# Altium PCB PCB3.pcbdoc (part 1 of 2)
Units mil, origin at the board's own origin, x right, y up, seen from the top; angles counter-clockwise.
Board outline 2248.24 x 2229.86 mil, 2 copper layers (Top Layer, Bottom Layer); 104 components, 71 nets, 405 pads, 227 vias.
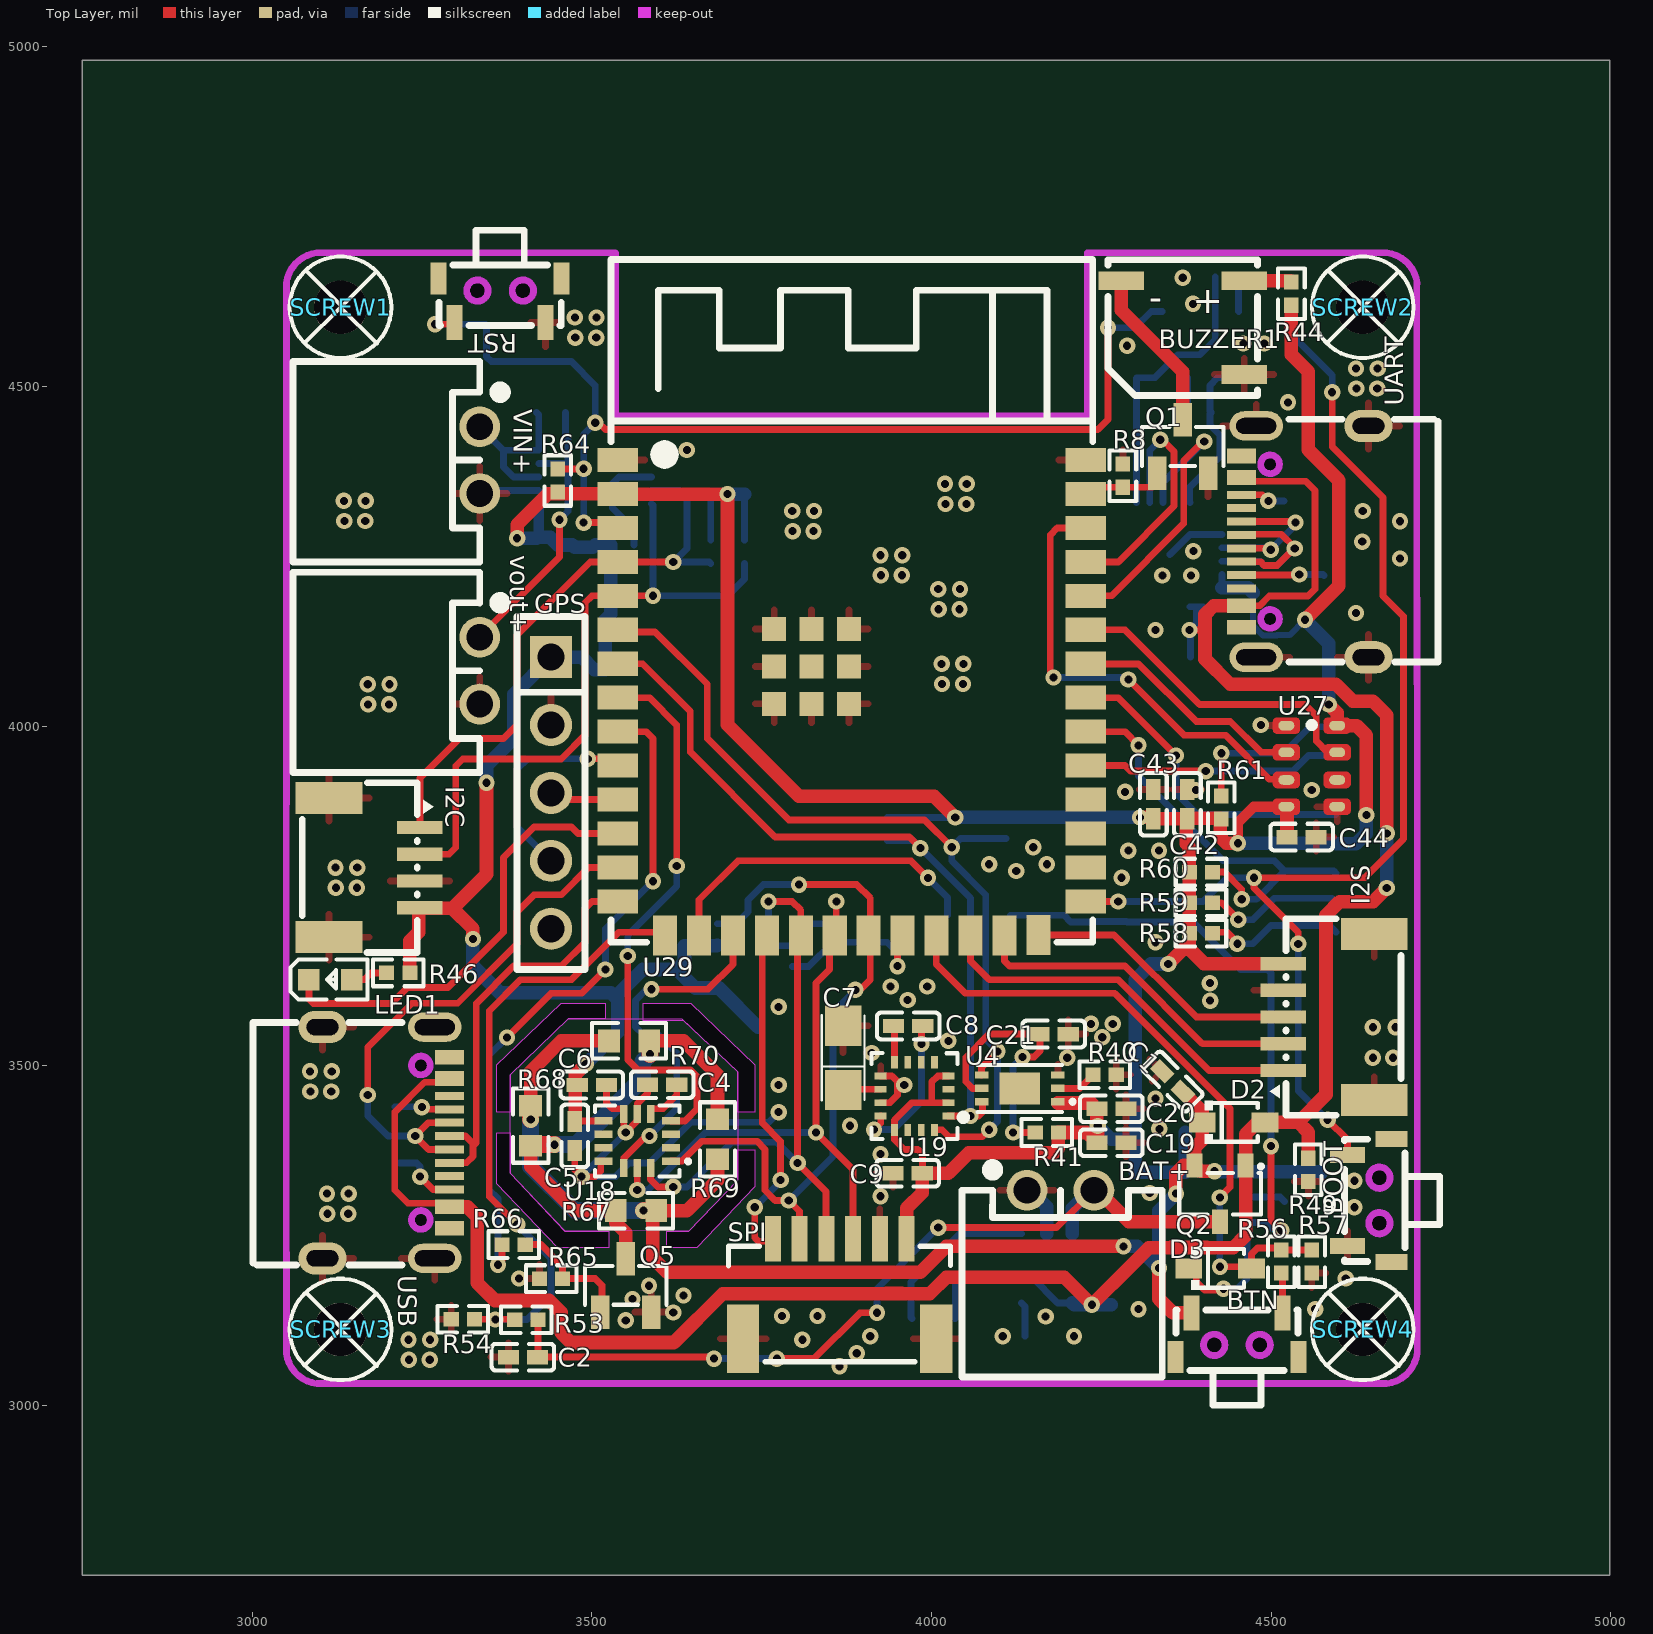
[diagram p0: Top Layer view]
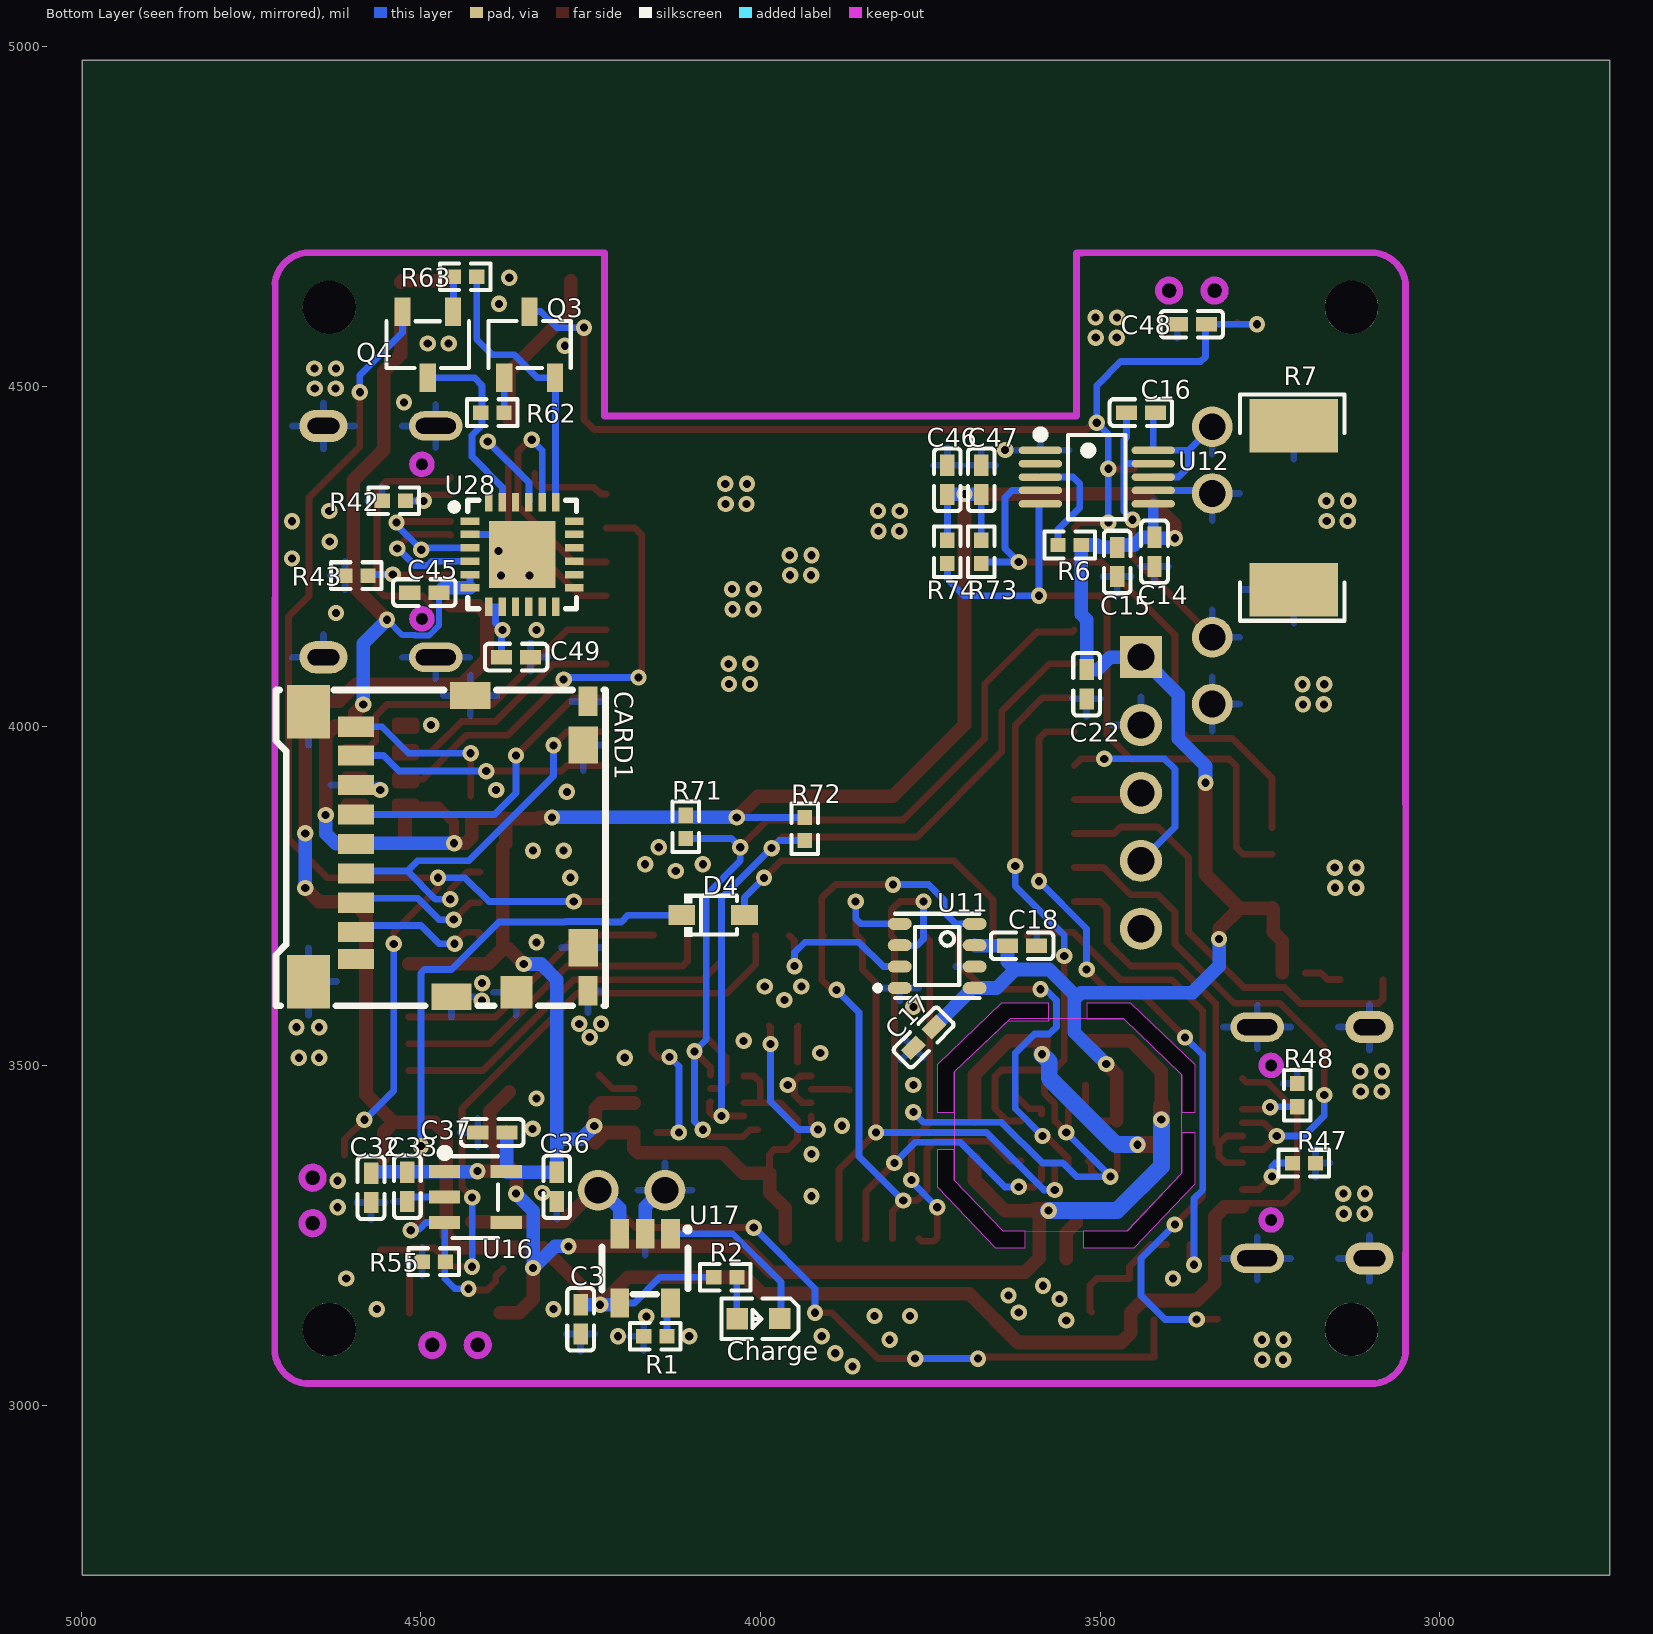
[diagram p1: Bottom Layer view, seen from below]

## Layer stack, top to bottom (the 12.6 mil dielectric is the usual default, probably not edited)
Top Layer: signal copper (thickness not stored)
Dielectric: dielectric 12.6, FR-4, Dk 4.8
Bottom Layer: signal copper (thickness not stored)

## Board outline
4998.24,2750 2750,2750 2750,4979.86 4998.24,4979.86
cut-out: 3519.88,3568.87 3464.93,3568.87 3379.88,3486.31 3379.88,3431.5 3359.99,3431.5 3359.99,3501.11 3455.02,3591.5 3519.88,3591.5
cut-out: 3379.8,3401.5 3379.8,3341.84 3460.07,3256.5 3524.88,3256.5 3524.88,3231.6 3450.03,3231.6 3359.88,3326.38 3359.88,3401.5
cut-out: 3715.09,3431.13 3715.09,3491.05 3635.26,3566.4 3575.33,3566.4 3575.33,3591.52 3645.34,3591.52 3739.88,3501.46 3739.88,3431.13
cut-out: 3609.99,3256.41 3642.26,3256.41 3714.88,3331.5 3714.88,3376.05 3740.01,3376.05 3740.01,3321.59 3654.37,3231.5 3609.99,3231.5

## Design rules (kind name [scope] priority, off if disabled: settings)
Clearance copperThickness1oz [All] p1: gap=7 ignorepadtopadclearanceinfootprint=FALSE except(4: Track-Track; 6: Track-SMDPad SMDPad-SMDPad Track-THPad SMDPad-THPad THPad-THPad Track-Via SMDPad-Via THPad-Via Via-Via SMDPad-Fill THPad-Fill Via-Fill Fill-Fill Track-Region SMDPad-Region THPad-Region Via-Region Region-Region Track-Poly SMDPad-Poly THPad-Poly Via-Poly Fill-Poly Region-Poly Poly-Poly Track-Text SMDPad-Text THPad-Text Via-Text Fill-Text Region-Text Poly-Text Text-Text; 6.9: Track-Hole SMDPad-Hole THPad-Hole Via-Hole Fill-Hole Region-Hole Poly-Hole Text-Hole Sheet-Hole; 11.8: Track-Fill Fill-Region Track-Sheet SMDPad-Sheet THPad-Sheet Via-Sheet Fill-Sheet Region-Sheet Poly-Sheet Text-Sheet)
Clearance copperThickness2oz [All] p1: gap=7 ignorepadtopadclearanceinfootprint=FALSE except(6: Track-SMDPad SMDPad-SMDPad Track-THPad SMDPad-THPad THPad-THPad Track-Via SMDPad-Via THPad-Via Via-Via SMDPad-Fill THPad-Fill Via-Fill Fill-Fill Track-Region SMDPad-Region THPad-Region Via-Region Region-Region Track-Poly SMDPad-Poly THPad-Poly Via-Poly Fill-Poly Region-Poly Poly-Poly Track-Text SMDPad-Text THPad-Text Via-Text Fill-Text Region-Text Poly-Text Text-Text; 6.9: Track-Hole SMDPad-Hole THPad-Hole Via-Hole Fill-Hole Region-Hole Poly-Hole Text-Hole Sheet-Hole; 8: Track-Track; 11.8: Track-Fill Fill-Region Track-Sheet SMDPad-Sheet THPad-Sheet Via-Sheet Fill-Sheet Region-Sheet Poly-Sheet Text-Sheet)
DiffPairsRouting differentialPair [All] p1: maxuncoupledlength=10 maxlimit=6 mostfreqgap=6 toplayer_minwidth=5 toplayer_prefwidth=10 toplayer_maxwidth=100 bottomlayer_minwidth=5 bottomlayer_prefwidth=10 bottomlayer_maxwidth=100
PasteMaskExpansion pasteMaskExpansion [All] p1:
PlaneConnect innerPlane [All] p1: planeconnectstyle=Relief reliefexpansion=20 reliefentries=4 reliefconductorwidth=10 reliefairgap=10
PolygonConnect copperRegion [All] p1: connectstyle=Relief reliefentries=4 reliefconductorwidth=10 polygonreliefangle="90 Angle" airgapwidth=10
RoutingVias viaSize [All] p1: viastyle="Through Hole" holewidth=12.0078 minholewidth=11.811 maxholewidth=248.0314 width=24.0158 minwidth=19.685 maxwidth=393.7008
SolderMaskExpansion solderMaskExpansion [All] p1: useseparateexpansions=TRUE expansion=2 expansionbottom=2
Width copperThickness1oz [All] p1: maxlimit=100 minlimit=5 preferedwidth=10
Width copperThickness2oz [All] p1: maxlimit=100 minlimit=8 preferedwidth=10

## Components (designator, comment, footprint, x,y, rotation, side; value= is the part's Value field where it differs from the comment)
BAT+ "XH2.54-2P_H弯针插座" CONN-TH_2P-P2.5_XH2.54-2P_H 4189.88,3316.5 r0 top
BOOT "1TS003B-1800-3500A-CT" SW-SMD_1TS003B-XXXX-3500A-CT#1 4644.88,3301.5 r270 top
BTN "1TS003B-1800-3500A-CT" SW-SMD_1TS003B-XXXX-3500A-CT#2 4449.81,3103.36 r180 top
BUZZER1 "MLT-5020" BUZ-SMD_L5.0-W5.5-P4.60 4369.88,4586.5 r180 top
C1 "CL05A106MQ5NUNC" C0402 4354.88,3476.5 r315 top
C2 "CL05A106MQ5NUNC" C0402 3398.5,3070.81 r180 top
C3 "CL05A106MQ5NUNC" C0402 4264.88,3126.5 r90 bottom
C4 "CC0402KRX7R7BB103" C0402 3603.5,3472.02 r180 top
C5 "CC0402KRX7R7BB104" C0402 3474.88,3396.5 r90 top
C6 "GRM155R61E225KE11D" C0402 3499.88,3471.5 r180 top
C7 "TAJA475K016RNJ" CASE-A_3216 3869.88,3511.5 r90 top
C8 "CL05B224KO5NNNC" C0402 3965.76,3558.36 r0 top
C9 "CC0402KRX7R7BB104" C0402 3964.88,3341.5 r0 top
C14 "CC0402KRX7R7BB104" C0402 3419.88,4256.5 r90 bottom
C15 "C1005X5R105KCTS" C0402 3474.88,4241.5 r90 bottom
C16 "CC0402KRX7R7BB104" C0402 3439.88,4461.5 r180 bottom
C17 "CC0402KRX7R7BB104" C0402 3759.88,3541.5 r135 bottom
C18 "C1005X5R105KCTS" C0402 3614.88,3676.5 r0 bottom
C19 "CC0402KRX7R7BB104" C0402 4264.88,3386.5 r180 top
C20 "C1005X5R105KCTS" C0402 4264.88,3436.5 r180 top
C21 "CC0402KRX7R7BB104" C0402 4179.88,3546.5 r180 top
C22 "CC0402KRX7R7BB104" C0402 3519.88,4061.5 r90 bottom
C32 "CL05A106MQ5NUNC" C0402 4573.42,3320.04 r90 bottom
C33 "CC0402KRX7R7BB104" C0402 4519.88,3321.5 r90 bottom
C36 "CL05A106MQ5NUNC" C0402 4299.88,3321.5 r90 bottom
C37 "CC0402KRX7R7BB104" C0402 4394.88,3401.5 r180 bottom
C42 "0603B104K500NT" C0402 4376.74,3884.9 r270 top
C43 "C1005X5R105KCTS" C0402 4326.74,3884.9 r270 top
C44 "CC0402KRX7R7BB104" C0402 4544.88,3836.5 r0 top
C45 "0603B104K500NT" C0402 4494.88,4196.5 r0 bottom
C46 "CC0402KRX7R7BB104" C0402 3724.88,4362.5 r90 bottom
C47 "C1005X5R105KCTS" C0402 3674.88,4362.5 r90 bottom
C48 "C1005X5R105KCTS" C0402 3364.88,4591.5 r0 bottom
C49 "CC0402KRX7R7BB104" C0402 4359.88,4101.5 r0 bottom
CARD1 "TF-110" TF-SMD_TF-110 4459.71,3823.2 r270 bottom
Charge "XL-1608SURC-06" LED0603-RD_RED 4002.88,3127.5 r0 bottom
D2 "1N5819WS_C191023" SOD-323_L1.8-W1.3-LS2.5-RD 4444.88,3416.5 r0 top
D3 "1N5819WS_C191023" SOD-323_L1.8-W1.3-LS2.5-RD 4424.88,3201.5 r0 top
D4 "1N5819WS_C191023" SOD-323_L1.8-W1.3-LS2.5-RD 4069.88,3721.5 r180 bottom
GPS "2.54-1*5P母" HDR-TH_5P-P2.54-V-F 3439.88,3901.5 r270 top
I2C "ZX-SH1.0-4PWT" CONN-SMD_4P-P1.00_MEGASTAR_ZX-SH1.0-4PWT 3179.88,3791.5 r270 top
I2S "ZX-SH1.0-5PWT" CONN-SMD_5P-P1.00_MEGASTAR_ZX-SH1.0-5PWT 4584.88,3571.5 r90 top
LED1 "XL-1608SURC-06" LED0603-RD_RED 3114.88,3626.5 r0 top
Q1 "SI2302-HXY" SOT-23-3_L2.9-W1.3-P1.90-LS2.4-BR 4369.88,4411.5 r270 top
Q2 "AO3401_C727156" SOT-23-3_L2.9-W1.4-P1.90-LS2.6-BR 4424.88,3311.5 r90 top
Q3 "S8050_C181158" SOT-23-3_L2.9-W1.6-P1.90-LS2.8-BR 4339.88,4561.5 r270 bottom
Q4 "S8050_C181158" SOT-23-3_L2.9-W1.6-P1.90-LS2.8-BR 4489.88,4561.5 r90 bottom
Q5 "AO3400A_C20917" SOT-23-3_L2.9-W1.3-P1.90-LS2.4-BR 3549.88,3176.5 r270 top
R1 "0402WGF2001TCE" R0402 4154.88,3101.5 r0 bottom
R2 "0402WGF3300TCE" R0402 4051.88,3188.5 r180 bottom
R6 "RTT02472JTH" R0402 3544.88,4266.5 r0 bottom
R7 "LRAN25EJER005" RES-SMD_L6.4-W3.2-R2512 3214.88,4321.5 r90 bottom
R8 "RC0402FR-0710KL" R0402 4281.88,4368.5 r270 top
R40 "RC0402FR-0710KL" R0402 4254.88,3486.5 r180 top
R41 "0402WGF1001TCE" R0402 4169.88,3401.5 r0 top
R42 "0402WGF5101TCE" R0402 4539.88,4331.5 r0 bottom
R43 "0402WGF5101TCE" R0402 4594.88,4221.5 r0 bottom
R44 "0402WGF220KTCE" R0402 4529.88,4636.5 r270 top
R46 "0402WGF1001TCE" R0402 3214.88,3636.5 r0 top
R47 "0402WGF5101TCE" R0402 3199.88,3356.5 r180 bottom
R48 "0402WGF5101TCE" R0402 3209.88,3456.5 r90 bottom
R49 "0402WGF2003TCE" R0402 4554.88,3346.5 r90 top
R53 "0402WGF5103TCE" R0402 3403.5,3125.81 r0 top
R54 "0402WGF5103TCE" R0402 3309.88,3126.5 r0 top
R55 "RC0402FR-0710KL" R0402 4480.88,3211.5 r180 bottom
R56 "0402WGF2001TCE" R0402 4514.88,3211.5 r90 top
R57 "0402WGF5101TCE" R0402 4559.88,3211.5 r270 top
R58 "RC0402FR-0710KL" R0402 4396.74,3694.9 r0 top
R59 "RC0402FR-0710KL" R0402 4396.74,3739.9 r0 top
R60 "RC0402FR-0710KL" R0402 4396.74,3784.9 r0 top
R61 "RC0402FR-0710KL" R0402 4426.74,3879.9 r90 top
R62 "RC0402FR-0710KL" R0402 4394.88,4461.5 r180 bottom
R63 "RC0402FR-0710KL" R0402 4434.88,4661.5 r0 bottom
R64 "RC0402FR-0710KL" R0402 3449.88,4361.5 r90 top
R65 "RC0402FR-0710KL" R0402 3439.88,3186.5 r180 top
R66 "0402WGJ0101TCE" R0402 3384.88,3236.5 r0 top
R67 "0603WAF510JT5E" R0603 3564.88,3286.5 r0 top
R68 "0603WAF510JT5E" R0603 3409.88,3411.5 r90 top
R69 "0603WAF510JT5E" R0603 3684.88,3391.5 r270 top
R70 "0603WAF510JT5E" R0603 3554.88,3536.5 r180 top
R71 "0402WGJ0472TCE" R0402 4109.88,3851.5 r90 bottom
R72 "0402WGJ0472TCE" R0402 3934.88,3848.5 r90 bottom
R73 "0402WGJ0472TCE" R0402 3674.88,4256.5 r270 bottom
R74 "0402WGJ0472TCE" R0402 3724.88,4256.5 r270 bottom
RST "1TS003B-1800-3500A-CT" SW-SMD_1TS003B-XXXX-3500A-CT#2 3364.88,4626.5 r0 top
SCREW1 "M2螺丝" M2螺丝 3129.88,4616.5 r0 top
SCREW2 "M2螺丝" M2螺丝 4634.88,4616.5 r0 top
SCREW3 "M2螺丝" M2螺丝 3129.88,3111.5 r0 top
SCREW4 "M2螺丝" M2螺丝 4634.88,3111.5 r0 top
SPI "AFC10-S06QCA-00" CONN-SMD_AFC10-S06QCA-00 3864.88,3171.5 r0 top
U4 "BH1750FVI-TR" WSOF-6_L2.6-W1.6-P0.50-TL-EP 4129.88,3466.5 r180 top
U11 "BME680" LGA-8_L3.0-W3.0-P0.80-TR 3739.88,3661.5 r0 bottom
U12 "INA226AIDGSR" MSOP-10_L3.0-W3.0-P0.50-LS5.0-BL 3504.88,4366.5 r270 bottom
U16 "RT9013-33GB" SOT-23-5_L3.0-W1.7-P0.95-LS2.8-BL 4419.88,3306.5 r270 bottom
U17 "TP4054_C668215" TSOT-23-5_L2.9-W1.6-P0.95-LS2.8-BR 4169.88,3201.5 r90 bottom
U18 "ICM-42688-P" LGA-14_L3.0-W2.5-P0.50-TL 3566.68,3389.08 r180 top
U19 "QMC5883L" LGA-16_L3.0-W3.0-P0.50-BL_SQ 3974.98,3455.25 r90 top
U27 "MSM261S4030H0" MSM-MIC 4559.88,3941.5 r180 top
U28 "CH9102F" QFN-24_L4.0-W4.0-P0.50-BL-EP2.5 4350.88,4252.5 r270 bottom
U29 "ESP32-S3-WROOM-1-N16R8" WIRELM-SMD_ESP32-S3-WROOM-1 3882.56,4041.5 r0 top
UART "TYPE-C 16PIN 2MD(073)" USB-C-SMD_TYPE-C-6PIN-2MD-073 4549.88,4271.5 r90 top
USB "TYPE-C 16PIN 2MD(073)" USB-C-SMD_TYPE-C-6PIN-2MD-073 3196.88,3386.5 r270 top
VIN+ "XH2.54-2P_H弯针插座" CONN-TH_2P-P2.5_XH2.54-2P_H 3334.88,4391.5 r270 top
vout+ "XH2.54-2P_H弯针插座" CONN-TH_2P-P2.5_XH2.54-2P_H 3334.88,4081.5 r270 top

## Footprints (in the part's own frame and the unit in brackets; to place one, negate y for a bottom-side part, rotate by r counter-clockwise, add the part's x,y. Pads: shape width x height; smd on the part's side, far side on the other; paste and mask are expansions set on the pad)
BUZ-SMD_L5.0-W5.5-P4.60 [mm]
  rect 1.7x0.7 smd: 1(-2.3,-1.75) 2(2.3,-1.75) 3(-2.3,1.75)
  silkscreen extent -2.79,-2.54 2.79,2.54
C0402 [mm]
  rect 0.79x0.54 smd: 1(-0.545,0) 2(0.545,0)
  silkscreen extent -1.17,-0.5 1.17,0.5
CASE-A_3216 [mil]
  rect 59.05x53.5 smd: 1(-47.24,0) 2(47.24,0)
  silkscreen extent -63,-32 63,32
CONN-SMD_4P-P1.00_MEGASTAR_ZX-SH1.0-4PWT [mm]
  rect 0.5x1.7 smd: 1(-1.5,1.7) 2(-0.5,1.7) 3(0.5,1.7) 4(1.5,1.7)
  rect 1.2x2.5 smd: 5(2.6,-1.7) 6(-2.6,-1.7)
  silkscreen extent -3.18,-2.7 3.18,2.21
CONN-SMD_5P-P1.00_MEGASTAR_ZX-SH1.0-5PWT [mm]
  rect 0.5x1.7 smd: 1(-2,1.7) 2(-1,1.7) 3(0,1.7) 4(1,1.7) 5(2,1.7)
  rect 1.2x2.5 smd: 6(3.1,-1.7) 7(-3.1,-1.7)
  silkscreen extent -3.67,-2.7 3.68,2.21
CONN-SMD_AFC10-S06QCA-00 [mm]
  rect 0.6x1.71 smd: 1(-2.5,1.87) 2(-1.5,1.87) 3(-0.5,1.87) 4(0.5,1.87) 5(1.5,1.87) 6(2.5,1.87)
  rect 1.2x2.55 smd: 7(3.61,-1.87) 8(-3.61,-1.87)
  silkscreen extent -4.16,-2.73 4.14,1.59
CONN-TH_2P-P2.5_XH2.54-2P_H [mil]
  round 60 hole 39.4: 1(-49.2,0) 2(49.2,0)
  silkscreen extent -145,-275 150,38
HDR-TH_5P-P2.54-V-F [mil]
  rect 62x62 hole 40.16: 1(-200,0)
  round 62 hole 40.16: 2(-100,0) 3(0,0) 4(100,0) 5(200,0)
  silkscreen extent -260,-50 260,50
LED0603-RD_RED [mm]
  rect 0.8x0.8 smd: 1(-0.8,-0.003) 2(0.8,0.003)
  silkscreen extent -1.49,-0.75 1.39,0.76
LGA-8_L3.0-W3.0-P0.80-TR [mm]
  oval 0.9x0.448 smd: 1(1.4,1.2) 2(1.4,0.4) 3(1.4,-0.4) 4(1.4,-1.2) 5(-1.4,-1.2) 6(-1.4,-0.4) 7(-1.4,0.4) 8(-1.4,1.2)
  silkscreen extent -1.58,-1.58 2.33,1.58
LGA-14_L3.0-W2.5-P0.50-TL [mm]
  rect 0.675x0.28 smd: 1(-1.262,0.75) 2(-1.262,0.25) 3(-1.262,-0.25) 4(-1.262,-0.75) 8(1.262,-0.75) 9(1.262,-0.25) 10(1.262,0.25) 11(1.262,0.75)
  rect 0.28x0.675 smd: 5(-0.5,-1.012) 6(0,-1.012) 7(0.5,-1.012) 12(0.5,1.012) 13(0,1.012) 14(-0.5,1.012)
  silkscreen extent -1.98,-1.33 1.58,1.33
LGA-16_L3.0-W3.0-P0.50-BL_SQ [mm]
  rect 0.25x0.45 smd: 1(-0.75,-1.263) 2(-0.25,-1.263) 3(0.25,-1.263) 4(0.75,-1.263) 9(0.75,1.263) 10(0.25,1.263) 11(-0.25,1.263) 12(-0.75,1.263)
  rect 0.45x0.25 smd: 5(1.263,-0.75) 6(1.263,-0.25) 7(1.263,0.25) 8(1.263,0.75) 13(-1.263,0.75) 14(-1.263,0.25) 15(-1.263,-0.25) 16(-1.263,-0.75)
  silkscreen extent -1.61,-1.95 1.61,1.6
M2螺丝 [mm]
  round 2 hole 2: 1(0,0)
  silkscreen extent -1.9,-1.9 1.9,1.9
MSM-MIC [mil]
  oval 23.64x14.16 smd: 1(-37.4,60.3) 3(-37.4,-19.7) 6(37.4,-19.7) 8(37.4,60.3)
  oval 23.64x14.22 smd: 2(-37.4,20.9) 4(-37.4,-59.1) 5(37.4,-59.1) 7(37.4,20.9)
  Top Layer region: -17.7,-13.8 -17.7,-25.6 -17.7,-25.6 -18.15,-27.86 -19.43,-29.77 -21.34,-31.05 -23.6,-31.5 -23.6,-31.5 -23.6,-31.5 -51.2,-31.5 -51.2,-31.5 -53.46,-31.05 -55.37,-29.77 -56.65,-27.86 -57.1,-25.6 -57.1,-25.6 -57.1,-25.6 -57.1,-13.8 -57.1,-13.8 -56.65,-11.54 -55.37,-9.63 -53.46,-8.35 -51.2,-7.9 -51.2,-7.9 -51.2,-7.9 -23.6,-7.9 -23.6,-7.9 -21.34,-8.35 -19.43,-9.63 -18.15,-11.54 -17.7,-13.8
  Top Layer region: -17.7,-53.1 -17.7,-65 -17.7,-65 -18.15,-67.26 -19.43,-69.17 -21.34,-70.45 -23.6,-70.9 -23.6,-70.9 -23.6,-70.9 -51.2,-70.9 -51.2,-70.9 -53.46,-70.45 -55.37,-69.17 -56.65,-67.26 -57.1,-65 -57.1,-65 -57.1,-65 -57.1,-53.1 -57.1,-53.1 -56.65,-50.84 -55.37,-48.93 -53.46,-47.65 -51.2,-47.2 -51.2,-47.2 -51.2,-47.2 -23.6,-47.2 -23.6,-47.2 -21.34,-47.65 -19.43,-48.93 -18.15,-50.84 -17.7,-53.1
  Top Layer region: -17.7,26.9 -17.7,15 -17.7,15 -18.15,12.74 -19.43,10.83 -21.34,9.55 -23.6,9.1 -23.6,9.1 -23.6,9.1 -51.2,9.1 -51.2,9.1 -53.46,9.55 -55.37,10.83 -56.65,12.74 -57.1,15 -57.1,15 -57.1,15 -57.1,26.9 -57.1,26.9 -56.65,29.16 -55.37,31.07 -53.46,32.35 -51.2,32.8 -51.2,32.8 -51.2,32.8 -23.6,32.8 -23.6,32.8 -21.34,32.35 -19.43,31.07 -18.15,29.16 -17.7,26.9
  Top Layer region: -17.7,66.2 -17.7,54.4 -17.7,54.4 -18.15,52.14 -19.43,50.23 -21.34,48.95 -23.6,48.5 -23.6,48.5 -23.6,48.5 -51.2,48.5 -51.2,48.5 -53.46,48.95 -55.37,50.23 -56.65,52.14 -57.1,54.4 -57.1,54.4 -57.1,54.4 -57.1,66.2 -57.1,66.2 -56.65,68.46 -55.37,70.37 -53.46,71.65 -51.2,72.1 -51.2,72.1 -51.2,72.1 -23.6,72.1 -23.6,72.1 -21.34,71.65 -19.43,70.37 -18.15,68.46 -17.7,66.2
  Top Layer region: 57.1,66.2 57.1,54.4 57.1,54.4 56.65,52.14 55.37,50.23 53.46,48.95 51.2,48.5 51.2,48.5 51.2,48.5 23.6,48.5 23.6,48.5 21.34,48.95 19.43,50.23 18.15,52.14 17.7,54.4 17.7,54.4 17.7,54.4 17.7,54.4 17.7,66.2 17.7,66.2 18.15,68.46 19.43,70.37 21.34,71.65 23.6,72.1 23.6,72.1 23.6,72.1 51.2,72.1 51.2,72.1 53.46,71.65 55.37,70.37 56.65,68.46 57.1,66.2
  Top Layer region: 57.1,26.9 57.1,15 57.1,15 56.65,12.74 55.37,10.83 53.46,9.55 51.2,9.1 51.2,9.1 51.2,9.1 23.6,9.1 23.6,9.1 21.34,9.55 19.43,10.83 18.15,12.74 17.7,15 17.7,15 17.7,15 17.7,15 17.7,26.9 17.7,26.9 18.15,29.16 19.43,31.07 21.34,32.35 23.6,32.8 23.6,32.8 23.6,32.8 51.2,32.8 51.2,32.8 53.46,32.35 55.37,31.07 56.65,29.16 57.1,26.9
  Top Layer region: 57.1,-53.1 57.1,-65 57.1,-65 56.65,-67.26 55.37,-69.17 53.46,-70.45 51.2,-70.9 51.2,-70.9 51.2,-70.9 23.6,-70.9 23.6,-70.9 21.34,-70.45 19.43,-69.17 18.15,-67.26 17.7,-65 17.7,-65 17.7,-65 17.7,-65 17.7,-53.1 17.7,-53.1 18.15,-50.84 19.43,-48.93 21.34,-47.65 23.6,-47.2 23.6,-47.2 23.6,-47.2 51.2,-47.2 51.2,-47.2 53.46,-47.65 55.37,-48.93 56.65,-50.84 57.1,-53.1
  Top Layer region: 57.1,-13.8 57.1,-25.6 57.1,-25.6 56.65,-27.86 55.37,-29.77 53.46,-31.05 51.2,-31.5 51.2,-31.5 51.2,-31.5 23.6,-31.5 23.6,-31.5 21.34,-31.05 19.43,-29.77 18.15,-27.86 17.7,-25.6 17.7,-25.6 17.7,-25.6 17.7,-25.6 17.7,-13.8 17.7,-13.8 18.15,-11.54 19.43,-9.63 21.34,-8.35 23.6,-7.9 23.6,-7.9 23.6,-7.9 51.2,-7.9 51.2,-7.9 53.46,-8.35 55.37,-9.63 56.65,-11.54 57.1,-13.8
  silkscreen extent -4,-64 4,-56
MSOP-10_L3.0-W3.0-P0.50-LS5.0-BL [mm]
  oval 0.28x1.62 smd: 1(-1,-2.11) 2(-0.5,-2.11) 3(0,-2.11) 4(0.5,-2.11) 5(1,-2.11) 6(1,2.11) 7(0.5,2.11) 8(0,2.11) 9(-0.5,2.11) 10(-1,2.11)
  silkscreen extent -1.74,-2.26 1.58,1.07
QFN-24_L4.0-W4.0-P0.50-BL-EP2.5 [mm]
  rect 0.28x0.7 smd: 1(-1.25,-1.95) 2(-0.75,-1.95) 3(-0.25,-1.95) 4(0.25,-1.95) 5(0.75,-1.95) 6(1.25,-1.95) 13(1.25,1.95) 14(0.75,1.95) 15(0.25,1.95) 16(-0.25,1.95) 17(-0.75,1.95) 18(-1.25,1.95)
  rect 0.7x0.28 smd: 7(1.95,-1.25) 8(1.95,-0.75) 9(1.95,-0.25) 10(1.95,0.25) 11(1.95,0.75) 12(1.95,1.25) 19(-1.95,1.25) 20(-1.95,0.75) 21(-1.95,0.25) 22(-1.95,-0.25) 23(-1.95,-0.75) 24(-1.95,-1.25)
  rect 2.5x2.5 smd: 25(0,0)
  silkscreen extent -2.03,-2.67 2.03,2.03
R0402 [mm]
  rect 0.566x0.54 smd: 1(-0.433,0) 2(0.433,0)
  silkscreen extent -0.94,-0.5 0.94,0.5
R0603 [mil]
  rect 31.75x34.02 smd: 1(-29.66,0) 2(29.66,0)
  silkscreen extent -55,-26 55,26
RES-SMD_L6.4-W3.2-R2512 [mm]
  rect 2x3.3 smd: 1(-3.066,0) 2(3.066,0)
  silkscreen extent -4.23,-1.91 4.23,2.01
SOD-323_L1.8-W1.3-LS2.5-RD [mm]
  rect 1x0.75 smd: 1(-1.173,0) 2(1.173,0)
  silkscreen extent -1.08,-0.8 0.9,0.8
SOT-23-3_L2.9-W1.3-P1.90-LS2.4-BR [mm]
  rect 1.25x0.7 smd: 1(1,-0.95) 2(1,0.95) 3(-1,0)
  silkscreen extent -0.73,-1.53 0.73,1.53
SOT-23-3_L2.9-W1.4-P1.90-LS2.6-BR [mm]
  rect 0.91x0.6 smd: 1(1.055,-0.955) 2(1.055,0.955) 3(-1.055,0)
  silkscreen extent -0.78,-1.6 1.09,1.53
SOT-23-3_L2.9-W1.6-P1.90-LS2.8-BR [mm]
  rect 1.07x0.6 smd: 1(1.235,-0.95) 2(1.235,0.95) 3(-1.235,0)
  silkscreen extent -0.88,-1.54 0.88,1.54
SOT-23-5_L3.0-W1.7-P0.95-LS2.8-BL [mm]
  rect 0.49x1.157 smd: 1(-0.95,-1.154) 2(0,-1.154) 3(0.95,-1.154)
  rect 0.49x1.175 smd: 4(0.95,1.154) 5(-0.95,1.154)
  silkscreen extent -1.8,-1.29 1.53,0.85
SW-SMD_1TS003B-XXXX-3500A-CT#1 [mm]
  rect 0.6x1.3 smd: 1(-1.7,-0.825) 2(1.7,-0.825)
  rect 0.6x1.2 smd: 3(2.3,0.825) 4(-2.3,0.825)
  Multi-Layer board cut-out: -0.85,0.77 -1.05,0.716 -1.196,0.57 -1.25,0.37 -1.196,0.17 -1.05,0.024 -0.85,-0.03 -0.85,-0.03 -0.676,0.01 -0.537,0.121 -0.46,0.281 -0.46,0.459 -0.537,0.619 -0.676,0.73 -0.85,0.77
  Multi-Layer board cut-out: 0.85,0.77 0.65,0.716 0.504,0.57 0.45,0.37 0.504,0.17 0.65,0.024 0.85,-0.03 0.85,-0.03 1.024,0.01 1.163,0.121 1.24,0.281 1.24,0.459 1.163,0.619 1.024,0.73 0.85,0.77
  Multi-Layer keep-out circle w0.254: c-0.85,0.37 r0.4
  Multi-Layer keep-out circle w0.254: c0.85,0.37 r0.4
  silkscreen extent -2.29,-0.94 2.29,2.63
SW-SMD_1TS003B-XXXX-3500A-CT#2 [mm]
  rect 0.6x1.3 smd: 1(-1.7,-0.825) 2(1.7,-0.825)
  rect 0.6x1.2 smd: 3(2.3,0.825) 4(-2.3,0.825)
  Multi-Layer board cut-out: -1.25,0.37 -1.195,0.171 -1.049,0.026 -0.85,-0.027 -0.651,0.026 -0.505,0.171 -0.45,0.37 -0.45,0.37 -0.505,0.569 -0.651,0.714 -0.85,0.767 -1.049,0.714 -1.195,0.569 -1.25,0.37
  Multi-Layer board cut-out: 0.45,0.37 0.505,0.171 0.651,0.026 0.85,-0.027 1.049,0.026 1.195,0.171 1.25,0.37 1.25,0.37 1.195,0.569 1.049,0.714 0.85,0.767 0.651,0.714 0.505,0.569 0.45,0.37
  Multi-Layer keep-out circle w0.254: c-0.85,0.37 r0.4
  Multi-Layer keep-out circle w0.254: c0.85,0.37 r0.4
  silkscreen extent -2.29,-0.94 2.29,2.63
TF-SMD_TF-110 [mil]
  rect 29.5x53.2 smd: 1(126.7,-136) 2(83.4,-136) 3(40.1,-136) 4(-3.2,-136) 5(-46.6,-136) 6(-89.9,-136) 7(-133.2,-136) 8(-175.7,-136) 9(166,-136)
  rect 47.2x47.2 smd: 10(215.2,100.2)
  rect 43.3x27.6 smd: 11(213.2,205.9) 14(-213.1,205.9)
  rect 55.1x43.3 smd: 12(149.4,198.6) 13(-148.9,198.6)
  rect 39.4x59.1 smd: 15(-221.7,32.3) 18(221.7,4.7)
  rect 78.7x63 smd: 16(-198.1,-205.9) 17(199.5,-205.9)
  silkscreen extent -230,-254 235,231
TSOT-23-5_L2.9-W1.6-P0.95-LS2.8-BR [mm]
  rect 1.1x0.7 smd: 1(1.294,-0.951) 2(1.294,-0.001) 3(1.294,0.951) 4(-1.294,0.951) 5(-1.294,-0.949)
  silkscreen extent -0.97,-1.65 1.52,1.61
USB-C-SMD_TYPE-C-6PIN-2MD-073 [mm]
  rect 0.55x1.1 smd: 1(-3.2,2.375) 2(-2.4,2.375) 11(2.4,2.375) 12(3.2,2.375)
  rect 0.3x1.1 smd: 3(-1.75,2.375) 4(-1.25,2.375) 5(-0.75,2.375) 6(-0.25,2.375) 7(0.25,2.375) 8(0.75,2.375) 9(1.25,2.375) 10(1.75,2.375)
  oval 1.2x1.8 hole 0.6 slot 1.2 at 90 deg: 13(-4.325,-2.375) 14(4.325,-2.375)
  oval 1.1x2 hole 0.6 slot 1.5 at 90 deg: 13(-4.325,1.825) 14(4.325,1.825)
  Multi-Layer board cut-out: -2.89,0.955 -2.716,1.003 -2.589,1.131 -2.543,1.305 -2.589,1.479 -2.716,1.607 -2.89,1.655 -2.89,1.655 -3.064,1.607 -3.191,1.479 -3.237,1.305 -3.191,1.131 -3.064,1.003 -2.89,0.955
  Multi-Layer board cut-out: 2.89,0.955 3.064,1.003 3.191,1.131 3.237,1.305 3.191,1.479 3.064,1.607 2.89,1.655 2.89,1.655 2.716,1.607 2.589,1.479 2.543,1.305 2.589,1.131 2.716,1.003 2.89,0.955
  Multi-Layer keep-out circle w0.254: c-2.89,1.305 r0.35
  Multi-Layer keep-out circle w0.254: c2.89,1.305 r0.35
  silkscreen extent -4.5,-4.97 4.57,0.6
WIRELM-SMD_ESP32-S3-WROOM-1 [mm]
  rect 1.5x0.9 smd: 1(-8.75,8.895) 2(-8.75,7.625) 3(-8.75,6.355) 4(-8.75,5.085) 5(-8.75,3.815) 6(-8.75,2.545) 7(-8.75,1.275) 8(-8.75,0.005) 9(-8.75,-1.265) 10(-8.75,-2.535) 11(-8.75,-3.805) 12(-8.75,-5.075) 13(-8.75,-6.345) 14(-8.75,-7.615) 27(8.75,-7.615) 28(8.75,-6.345) 29(8.75,-5.075) 30(8.75,-3.805) 31(8.75,-2.535) 32(8.75,-1.265) 33(8.75,0.005) 34(8.75,1.275) 35(8.75,2.545) 36(8.75,3.815) 37(8.75,5.085) 38(8.75,6.355) 39(8.75,7.625) 40(8.75,8.895)
  rect 0.9x1.5 smd: 15(-6.985,-8.895) 16(-5.715,-8.895) 17(-4.445,-8.895) 18(-3.175,-8.895) 19(-1.905,-8.895) 20(-0.635,-8.895) 21(0.635,-8.895) 22(1.905,-8.895) 23(3.175,-8.895) 24(4.445,-8.895) 25(5.715,-8.895) 26(6.985,-8.865)
  rect 0.9x0.9 smd: 41(-2.9,-0.225) 41(-2.9,1.175) 41(-2.9,2.575) 41(-1.5,-0.225) 41(-1.5,1.175) 41(-1.5,2.575) 41(-0.1,-0.225) 41(-0.1,1.175) 41(-0.1,2.575)
  silkscreen extent -9,-9.14 9.02,16.39
WSOF-6_L2.6-W1.6-P0.50-TL-EP [mm]
  rect 0.505x0.28 smd: 1(-1.427,0.5) 2(-1.427,0) 3(-1.427,-0.5) 4(1.427,-0.5) 5(1.427,0) 6(1.427,0.5)
  rect 1.5x1.2 smd: 7(0,0)
  silkscreen extent -2.05,-0.88 1.58,0.88

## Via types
v1: diameter 24.02, hole 12.01, Top Layer to Bottom Layer, 222 vias
v2: diameter 24, hole 12, Top Layer to Bottom Layer, 5 vias

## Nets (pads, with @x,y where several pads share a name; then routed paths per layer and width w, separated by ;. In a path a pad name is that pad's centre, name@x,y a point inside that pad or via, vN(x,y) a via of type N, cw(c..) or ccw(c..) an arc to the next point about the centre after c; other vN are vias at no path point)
3.3V: C5.2 C6.2 C9.2 C14.2 C15.2 C17.2 C18.2 C19.2 C20.2 C22.2 C36.2 C37.2 C42.2 C43.2 C44.1 C45.1 C46.1 C47.1 CARD1.4 GPS.1 I2C.4 I2S.5 R6.1 R41.2 R44.2 R46.2 R58.1 R59.1 R60.1 R61.1 R64.1 R71.2 R72.2 R73.1 R74.1 SPI.6 U4.1 U11.6 U11.8 U12.6 U16.5 U18.8 U19.2 U19.4 U19.13 U27.4 U27.8 U28.5 U28.6 U29.2 | length 6936.2
  Top Layer w10: C5.2@3474.88,3417.96 3475.54,3418.61 U18.8@3516.99,3418.61 ; C9.2@3986.34,3341.5 3986.96,3342.11 3986.96,3369.43 3979.88,3376.5 3959.88,3376.5 3945.45,3390.93 U19.13@3945.45,3405.53 3945.45,3419.67 3969.29,3443.51 3969.41,3443.51 3971.32,3445.42 4000.87,3445.42 ; U19.2@4024.7,3445.42 4000.87,3445.42 ; U19.4@4024.7,3484.79 4009.31,3484.79 4000.31,3475.79 4000.31,3445.98 4000.87,3445.42
  Top Layer w15: v1(4451.12,3827.5) 4451.12,3857.74 4474.58,3881.2 U27.8@4522.48,3881.2
  Top Layer w20: R46.2@3231.92,3636.5 3231.92,3683.54 3244.88,3696.5 3244.88,3730.51 I2C.4@3246.81,3732.44 3247.75,3731.5 3294.88,3731.5 ; v1(3324.88,3686.5) 3324.88,3701.5 3294.88,3731.5 ; v1(3344.88,3916.5) 3344.88,3781.5 3294.88,3731.5 ; v1(3389.88,4276.5) 3389.88,4296.5 3435.08,4341.69 U29.2@3538.07,4341.69 3538.27,4341.5 v1(3699.61,4341.5) 3699.61,4001.77 3804.88,3896.5 4003.83,3896.5 v1(4034.88,3865.44) ; C5.2@3475.54,3418.61 3475.54,3486.88 v1(3490.99,3502.33) ; SPI.6@3963.31,3245.12 3963.31,3289.93 3986.34,3312.96 C9.2@3986.34,3341.5 4024.88,3341.5 4054.88,3371.5 4179.88,3371.5 4186.92,3378.54 R41.2@4186.92,3401.5 4228.42,3401.5 C19.2@4243.42,3386.5 4244.87,3387.95 v1(4244.87,3411.13) 4243.42,3412.58 C20.2@4243.42,3436.5 4234.93,3445 U4.1@4186.08,3445 ; v1(4307.11,3865.44) 4324.74,3865.44 C43.2@4326.74,3863.44 C42.2@4375.08,3863.44 ; v1(4348.64,3649.59) 4370.73,3671.68 4379.7,3671.68 ; C42.2@4376.74,3863.44 C42.2@4375.08,3863.44 ; v1(4451.12,3827.5) 4434.15,3827.5 4425.08,3836.57 4425.08,3864.5 4375.08,3864.5 C42.2@4375.08,3863.44 ; I2S.5@4517.95,3650.24 4401.14,3650.24 4379.7,3671.68 ; U27.8@4522.48,3881.2 4523.42,3880.26 C44.1@4523.42,3836.5 ; R44.2@4529.88,4619.46 4529.88,4546.5 4554.88,4521.5 4554.88,4406.5 4599.88,4361.5 4599.88,4206.5 v1(4549.88,4156.5) ; v1(4584.88,4031.64) 4597.28,4019.24 U27.4@4597.28,4000.6 4625.78,4000.6 4640.31,3986.08 v1(4640.31,3868.96) ; C42.2@4375.08,3863.44 4375.08,3826.57 4379.7,3821.94 R60.1@4379.7,3784.9 R59.1@4379.7,3739.9 R58.1@4379.7,3694.9 4379.7,3671.68
  Bottom Layer w9: C45.1@4473.42,4196.5 4473.42,4147.79 4487.35,4133.86 4488.06,4133.86 4488.46,4133.46 4508.56,4133.46 4508.96,4133.86 4527.25,4133.86 v1(4549.88,4156.5)
  Bottom Layer w10: R73.1@3674.88,4273.54 3674.88,4340.04 C47.1@3674.88,4341.04 ; R74.1@3724.88,4273.54 C46.1@3724.88,4341.04 ; R72.2@3934.88,3865.54 3934.98,3865.44 v1(4034.88,3865.44) ; U28.6@4427.66,4203.28 U28.5@4427.66,4222.97
  Bottom Layer w15: C14.2@3419.88,4277.96 3421.81,4279.89 U12.6@3421.81,4327.13
  Bottom Layer w20: v1(3324.88,3686.5) 3324.88,3646.5 3363.9,3607.48 3527.81,3607.48 3531.59,3603.7 ; v1(3344.88,3916.5) 3344.88,3941.5 3384.88,3981.5 3384.88,4046.5 GPS.1@3439.88,4101.5 3484.88,4101.5 3503.42,4082.96 C22.2@3519.88,4082.96 3519.88,4156.5 3527.84,4164.46 R6.1@3527.84,4266.5 3504.88,4266.5 3501.34,4262.96 C15.2@3474.88,4262.96 3471.34,4266.5 3449.88,4266.5 3438.42,4277.96 C14.2@3419.88,4277.96 3418.42,4276.5 v1(3389.88,4276.5) ; v1(3490.99,3502.33) 3537.94,3549.28 3537.94,3597.36 3531.59,3603.7 ; C47.1@3674.88,4340.04 3676.34,4341.5 v1(3699.61,4341.5) 3724.42,4341.5 C46.1@3724.88,4341.04 ; U11.6@3684.77,3677.25 3684.02,3676.5 C18.2@3636.34,3676.5 3636.34,3652.96 3624.88,3641.5 ; C17.2@3744.71,3556.67 3687.12,3614.26 U11.8@3684.77,3614.26 3652.12,3614.26 3624.88,3641.5 ; v1(4034.88,3865.44) v1(4307.11,3865.44) ; v1(4244.87,3411.13) 4264.5,3391.5 4299.88,3391.5 ; v1(4348.64,3649.59) 4322.98,3649.59 4299.88,3626.5 4299.88,3391.5 ; C37.2@4373.42,3401.5 4373.42,3344.94 U16.5@4374.46,3343.9 4373.52,3342.96 C36.2@4299.88,3342.96 4299.88,3391.5 ; U28.6@4427.66,4203.28 4466.64,4203.28 C45.1@4473.42,4196.5 ; v1(4451.12,3827.5) 4594.61,3827.5 CARD1.4@4595.71,3826.4 4624.79,3826.4 4639.88,3841.5 4639.88,3868.54 v1(4640.31,3868.96) ; v1(4549.88,4156.5) 4584.88,4121.5 v1(4584.88,4031.64) ; 3531.59,3603.7 3537.09,3603.7 3574.88,3641.5 3624.88,3641.5
3.3V_EN: D3.1 D4.1 R55.2 U16.3 | length 1053.8
  Top Layer w10: D3.1@4378.72,3201.5 4389.88,3190.33 4389.88,3181.77 4402.23,3169.43 4427.81,3169.43 v1(4429.88,3171.5) ; v1(4499.88,3381.5) 4499.88,3272.76 v1(4514.97,3257.67)
  Bottom Layer w10: D4.1@4116.05,3721.5 4194.88,3721.5 4204.88,3711.5 4234.08,3711.5 4234.91,3712.33 4287.31,3712.33 4288.15,3711.5 4384.88,3711.5 4454.88,3641.5 4494.88,3641.5 4499.88,3636.5 v1(4499.88,3381.5) ; v1(4429.88,3171.5) 4449.88,3171.5 4464.88,3186.5 4464.88,3210.46 R55.2@4463.84,3211.5 ; R55.2@4464.88,3214.46 4464.88,3268.68 U16.3@4465.3,3269.1 4492.28,3269.1 4502.28,3259.1 4513.54,3259.1 v1(4514.97,3257.67) ; R55.2@4465.84,3213.5 R55.2@4467.84,3211.5
$1N4694: R1.1 U17.5 | length 51.3
  Bottom Layer w10: U17.5@4132.52,3150.55 4137.84,3145.23 R1.1@4137.84,3101.5
$1N5288: Charge.1 U17.1 | length 246.4
  Bottom Layer w10: Charge.1@3971.4,3127.63 3969.88,3129.15 3969.88,3181.5 4040.83,3252.44 U17.1@4132.44,3252.44
$1N5387: Charge.2 R2.2 | length 61.3
  Bottom Layer w10: Charge.2@4034.36,3127.36 4034.84,3127.85 R2.2@4034.84,3188.5
$1N6161: C7.1 U19.10 | length 55.7
  Top Layer w10: C7.1@3869.88,3464.26 3870.71,3465.09 U19.10@3925.25,3465.09
$1N6282: C8.1 U19.8 | length 53.9
  Top Layer w10: C8.1@3944.3,3558.36 3945.44,3557.21 U19.8@3945.44,3504.98
$1N9067: R6.2 U12.3 | length 165.5
  Bottom Layer w10: R6.2@3561.92,4266.5 3561.92,4289.46 3529.88,4321.5 3529.88,4356.5 3539.88,4366.5 U12.3@3587.95,4366.5
$1N9978: BUZZER1.2 Q1.3 | length 242
  Top Layer w20: BUZZER1.2@4279.33,4655.39 4279.33,4612.05 4369.88,4521.5 Q1.3@4369.88,4450.87
$1N12524: R40.2 U4.2 | length 60
  Top Layer w10: U4.2@4186.08,3466.49 4217.84,3466.49 R40.2@4237.84,3486.5
$1N12564: C21.2 R41.1 U4.5 | length 390.1
  Top Layer w10: U4.5@4073.68,3466.49 4060.42,3466.49 4050.42,3476.49 4050.42,3512.03 4084.88,3546.5 C21.2@4158.42,3546.5 4159.88,3545.04 4159.88,3521.5 4151.18,3512.8 v1(4133.87,3512.8) ; v1(4120.14,3401.5) R41.1@4152.84,3401.5
  Bottom Layer w10: v1(4120.14,3401.5) 4120.14,3499.07 v1(4133.87,3512.8)
$1N18150: R43.1 UART.4 | length 122.4
  Top Layer w10: UART.4@4456.38,4222.29 4540.68,4222.29 v1(4541.43,4223.04)
  Bottom Layer w10: v1(4541.43,4223.04) 4576.3,4223.04 R43.1@4577.84,4221.5
$1N18154: R42.1 UART.10 | length 66.2
  Top Layer w10: UART.10@4456.38,4340.4 4487.12,4340.4 v1(4496.02,4331.5)
  Bottom Layer w10: v1(4496.02,4331.5) R42.1@4518.84,4331.5
$1N22569: BUZZER1.1 R44.1 | length 70.2
  Top Layer w20: BUZZER1.1@4460.43,4655.39 4528.03,4655.39 R44.1@4529.88,4653.54
$1N23357: LED1.2 R46.1 | length 55.6
  Top Layer w10: LED1.2@3146.36,3626.64 3165.02,3626.64 3174.88,3636.5 R46.1@3197.84,3636.5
